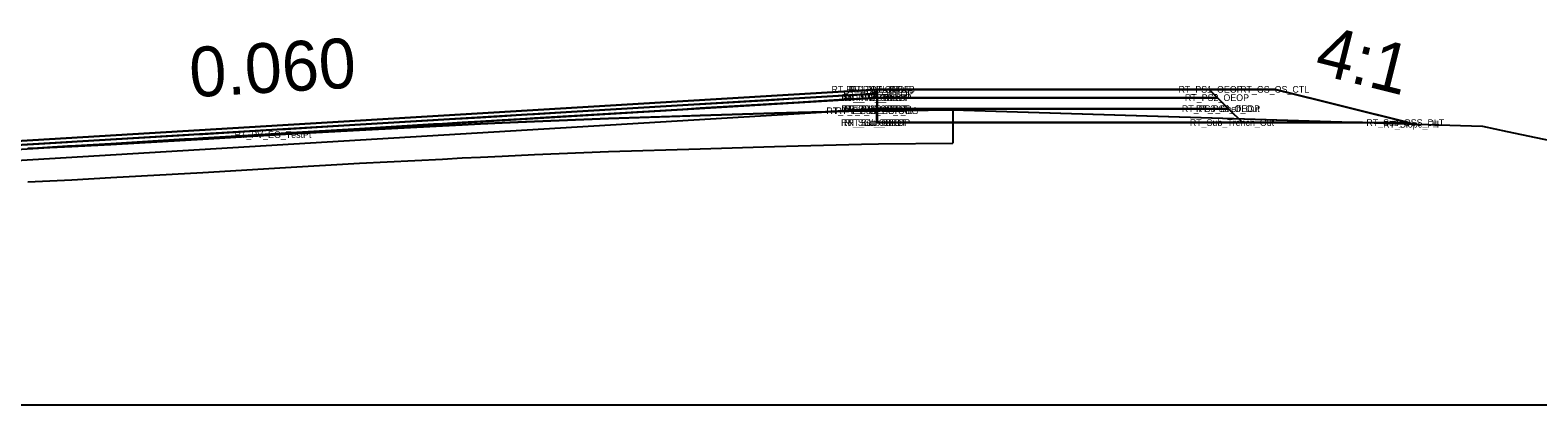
# Model space of a CAD drawing. Extents: x 2177029 to 2201446, y 59897 to 78390.
# Drawn here: x 2199283.21 to 2199328.65, y 69407.31 to 69418.59 of the extents above; entities that cross this region are included whole.
import ezdxf

# ---------------------------------------------------------------- set-up
doc = ezdxf.new("R2010")
doc.units = 0
for name, color, linetype in [('Exist Cross Section Cell', 7, 'Continuous'), ('Exist PHM Roadway Shape', 7, 'Continuous'), ('Exist XS Ground Line', 7, 'Continuous'), ('Old_Level_11', 7, 'Continuous'), ('Prop CMT Conc Surface', 7, 'Continuous'), ('Prop CMT Concrete Structures', 7, 'Continuous'), ('Prop CMT Guardrail Graphics', 7, 'Continuous'), ('Prop CMT Guardrail Widen Shoulder', 7, 'Continuous'), ('Prop CMT Pvmt Course 1', 7, 'Continuous'), ('Prop CMT Pvmt Course 1 CG', 7, 'Continuous'), ('Prop CMT Pvmt Course 2', 7, 'Continuous'), ('Prop CMT Pvmt Course 2 CG', 7, 'Continuous'), ('Prop CMT Pvmt Course 2 Wedge', 7, 'Continuous'), ('Prop CMT Pvmt Course 3', 7, 'Continuous'), ('Prop CMT Pvmt Course 4', 7, 'Continuous'), ('Prop CMT Pvmt Surface', 7, 'Continuous'), ('Prop CMT Pvmt Wedge Surface 1', 7, 'Continuous'), ('Prop CMT Slope Grass', 7, 'Continuous'), ('Prop CMT Subgrade Earthwork', 7, 'Continuous'), ('Prop Hatching', 7, 'Continuous'), ('Prop XS Side Slope Text', 7, 'Continuous'), ('Scratch_Level_0', 7, 'Continuous'), ('Scratch_Level_9', 7, 'Continuous')]:
    doc.layers.add(name, color=color, linetype=linetype)

msp = doc.modelspace()

# ---------------------------------------------------------------- linework, layer by layer
at = {"layer": 'Exist Cross Section Cell'}
msp.add_line((2199242.732, 69407.31), (2199442.732, 69407.31), dxfattribs=at)
at = {"layer": 'Exist XS Ground Line'}
msp.add_lwpolyline([(2199283.138, 69415.025), (2199284.462, 69415.09), (2199285.637, 69415.152), (2199288.411, 69415.307), (2199290.909, 69415.457), (2199293.137, 69415.583), (2199295.638, 69415.711), (2199296.227, 69415.744), (2199296.781, 69415.771), (2199297.43, 69415.802), (2199298.405, 69415.846), (2199300.637, 69415.937), (2199303.403, 69416.022), (2199305.638, 69416.094), (2199306.357, 69416.112), (2199308.264, 69416.161), (2199308.774, 69416.166), (2199311.018, 69416.191), (2199326.316, 69415.718), (2199326.976, 69415.698), (2199327.719, 69415.539), (2199346.356, 69411.643)], dxfattribs=at)
at = {"layer": 'Prop CMT Conc Surface'}
for points in [[(2199272.732, 69414.524), (2199308.732, 69416.684)], [(2199308.732, 69416.559), (2199308.732, 69416.809)], [(2199308.732, 69416.684), (2199308.732, 69416.559), (2199308.732, 69416.559)]]:
    msp.add_lwpolyline(points, dxfattribs=at)
at = {"layer": 'Prop CMT Concrete Structures'}
for p, q in [((2199272.732, 69414.649), (2199308.732, 69416.809)), ((2199308.732, 69416.809), (2199308.74, 69416.809)), ((2199308.74, 69416.809), (2199308.741, 69416.809))]:
    msp.add_line(p, q, dxfattribs=at)
at = {"layer": 'Prop CMT Guardrail Graphics'}
for points in [[(2199308.732, 69416.225), (2199308.732, 69416.809)], [(2199272.732, 69414.065), (2199308.732, 69416.225)]]:
    msp.add_lwpolyline(points, dxfattribs=at)
at = {"layer": 'Prop CMT Pvmt Course 1'}
for points in [[(2199308.732, 69416.226), (2199308.264, 69416.198), (2199307.969, 69416.18), (2199307.741, 69416.167), (2199307.176, 69416.133), (2199306.356, 69416.112), (2199305.638, 69416.094), (2199303.403, 69416.022), (2199303.138, 69416.013), (2199302.873, 69416.005), (2199300.637, 69415.937), (2199298.405, 69415.846), (2199298.138, 69415.835), (2199297.43, 69415.802), (2199296.781, 69415.771), (2199296.227, 69415.744), (2199295.638, 69415.711), (2199295.369, 69415.697), (2199293.137, 69415.583), (2199290.909, 69415.457), (2199290.638, 69415.442), (2199288.411, 69415.307), (2199288.138, 69415.291), (2199287.865, 69415.275), (2199285.637, 69415.152), (2199284.572, 69415.096), (2199284.474, 69415.091), (2199284.468, 69415.091), (2199284.462, 69415.09), (2199284.455, 69415.09), (2199284.449, 69415.09), (2199284.339, 69415.084), (2199283.281, 69415.032)], [(2199284.339, 69415.096), (2199284.449, 69415.102), (2199284.455, 69415.103), (2199284.462, 69415.103), (2199284.468, 69415.104), (2199284.474, 69415.104), (2199284.572, 69415.11), (2199285.637, 69415.174), (2199287.865, 69415.307), (2199288.138, 69415.324), (2199288.411, 69415.34), (2199290.638, 69415.474), (2199290.909, 69415.49), (2199293.137, 69415.624), (2199295.369, 69415.758), (2199295.638, 69415.774), (2199296.227, 69415.809), (2199296.781, 69415.842), (2199297.43, 69415.881), (2199298.138, 69415.924), (2199298.405, 69415.94), (2199300.637, 69416.074), (2199302.873, 69416.208), (2199303.138, 69416.224), (2199303.403, 69416.24), (2199305.638, 69416.374), (2199306.356, 69416.417), (2199307.741, 69416.5), (2199307.969, 69416.514), (2199308.264, 69416.531), (2199308.732, 69416.559)], [(2199308.732, 69416.559), (2199308.732, 69416.226)], [(2199283.281, 69415.032), (2199284.339, 69415.096)]]:
    msp.add_lwpolyline(points, dxfattribs=at)
at = {"layer": 'Prop CMT Pvmt Course 1 CG'}
for points in [[(2199308.741, 69416.226), (2199319.325, 69416.226)], [(2199308.741, 69415.809), (2199308.741, 69416.226)], [(2199319.325, 69416.226), (2199319.325, 69416.226)], [(2199319.325, 69416.226), (2199319.742, 69415.809)], [(2199319.742, 69415.809), (2199308.741, 69415.809)]]:
    msp.add_lwpolyline(points, dxfattribs=at)
at = {"layer": 'Prop CMT Pvmt Course 2'}
for points in [[(2199308.732, 69416.225), (2199308.741, 69416.226)], [(2199308.732, 69415.809), (2199308.732, 69416.225)], [(2199308.732, 69416.225), (2199308.732, 69416.225), (2199308.732, 69415.809), (2199308.732, 69415.809)], [(2199308.732, 69415.809), (2199308.732, 69416.225)], [(2199308.741, 69416.226), (2199308.741, 69415.809)], [(2199308.741, 69415.809), (2199308.732, 69415.809)]]:
    msp.add_lwpolyline(points, dxfattribs=at)
at = {"layer": 'Prop CMT Pvmt Course 2 CG'}
for points in [[(2199272.732, 69414.649), (2199308.732, 69416.809)], [(2199308.732, 69416.684), (2199272.732, 69414.524)], [(2199308.732, 69416.809), (2199308.741, 69416.809)], [(2199308.732, 69416.559), (2199308.732, 69416.809)], [(2199308.732, 69416.809), (2199308.732, 69416.559), (2199308.732, 69416.559), (2199308.732, 69416.684)], [(2199308.741, 69416.809), (2199308.741, 69416.559)], [(2199308.741, 69416.559), (2199308.732, 69416.559)]]:
    msp.add_lwpolyline(points, dxfattribs=at)
at = {"layer": 'Prop CMT Pvmt Course 2 Wedge'}
for points in [[(2199308.732, 69416.166), (2199308.264, 69416.161), (2199307.969, 69416.153), (2199307.741, 69416.147), (2199307.195, 69416.133)], [(2199307.195, 69416.133), (2199307.741, 69416.166)], [(2199307.741, 69416.166), (2199307.969, 69416.18), (2199308.264, 69416.197), (2199308.732, 69416.225)], [(2199308.732, 69416.225), (2199308.732, 69416.166)]]:
    msp.add_lwpolyline(points, dxfattribs=at)
at = {"layer": 'Prop CMT Pvmt Course 3'}
for points in [[(2199308.732, 69415.809), (2199308.717, 69416.165)], [(2199308.732, 69415.809), (2199308.741, 69415.809)], [(2199308.732, 69415.809), (2199308.732, 69415.809)], [(2199308.741, 69415.809), (2199319.742, 69415.809)], [(2199319.742, 69415.809), (2199324.742, 69415.809)]]:
    msp.add_lwpolyline(points, dxfattribs=at)
at = {"layer": 'Prop CMT Pvmt Course 4'}
msp.add_lwpolyline([(2199308.741, 69416.809), (2199318.742, 69416.809)], dxfattribs=at)
at = {"layer": 'Prop CMT Pvmt Surface'}
for points in [[(2199283.138, 69415.149), (2199284.339, 69415.221), (2199284.449, 69415.227), (2199284.455, 69415.228), (2199284.462, 69415.228), (2199284.468, 69415.229), (2199284.474, 69415.229), (2199284.572, 69415.235), (2199285.637, 69415.299), (2199287.865, 69415.432), (2199288.138, 69415.449), (2199288.411, 69415.465), (2199290.638, 69415.599), (2199290.909, 69415.615), (2199293.137, 69415.749), (2199295.369, 69415.883), (2199295.638, 69415.899), (2199296.227, 69415.934), (2199296.781, 69415.967), (2199297.43, 69416.006), (2199298.138, 69416.049), (2199298.405, 69416.065), (2199300.637, 69416.199), (2199302.873, 69416.333), (2199303.138, 69416.349), (2199303.403, 69416.365), (2199305.638, 69416.499), (2199306.356, 69416.542), (2199307.741, 69416.625), (2199307.969, 69416.639), (2199308.264, 69416.656), (2199308.732, 69416.684)], [(2199308.732, 69416.684), (2199308.732, 69416.559)], [(2199308.732, 69416.559), (2199308.264, 69416.531), (2199307.969, 69416.514), (2199307.741, 69416.5), (2199306.356, 69416.417), (2199305.638, 69416.374), (2199303.403, 69416.24), (2199303.138, 69416.224), (2199302.873, 69416.208), (2199300.637, 69416.074), (2199298.405, 69415.94), (2199298.138, 69415.924), (2199297.43, 69415.881), (2199296.781, 69415.842), (2199296.227, 69415.809), (2199295.638, 69415.774), (2199295.369, 69415.758), (2199293.137, 69415.624), (2199290.909, 69415.49), (2199290.638, 69415.474), (2199288.411, 69415.34), (2199288.138, 69415.324), (2199287.865, 69415.307), (2199285.637, 69415.174), (2199284.572, 69415.11), (2199284.474, 69415.104), (2199284.468, 69415.104), (2199284.462, 69415.103), (2199284.455, 69415.103), (2199284.449, 69415.102), (2199284.339, 69415.096), (2199283.281, 69415.032), (2199283.138, 69415.025)]]:
    msp.add_lwpolyline(points, dxfattribs=at)
at = {"layer": 'Prop CMT Pvmt Wedge Surface 1'}
for p, q in [((2199311.018, 69416.191), (2199311.018, 69415.191)), ((2199296.781, 69414.771), (2199297.43, 69414.802)), ((2199297.43, 69414.802), (2199298.405, 69414.846)), ((2199298.405, 69414.846), (2199300.637, 69414.937)), ((2199300.637, 69414.937), (2199303.403, 69415.022)), ((2199303.403, 69415.022), (2199305.638, 69415.094)), ((2199305.638, 69415.094), (2199306.357, 69415.112)), ((2199306.357, 69415.112), (2199308.264, 69415.161)), ((2199308.264, 69415.161), (2199308.774, 69415.166)), ((2199308.774, 69415.166), (2199311.018, 69415.191)), ((2199311.018, 69415.191), (2199311.018, 69415.191)), ((2199288.411, 69414.307), (2199290.909, 69414.457)), ((2199290.909, 69414.457), (2199293.137, 69414.583)), ((2199293.137, 69414.583), (2199295.638, 69414.711)), ((2199295.638, 69414.711), (2199296.227, 69414.744)), ((2199296.227, 69414.744), (2199296.781, 69414.771)), ((2199283.138, 69414.025), (2199284.462, 69414.09)), ((2199284.462, 69414.09), (2199285.637, 69414.152)), ((2199285.637, 69414.152), (2199288.411, 69414.307))]:
    msp.add_line(p, q, dxfattribs=at)
at = {"layer": 'Prop CMT Slope Grass'}
for points in [[(2199308.732, 69416.225), (2199308.732, 69416.559)], [(2199308.732, 69416.559), (2199308.741, 69416.559)], [(2199308.732, 69416.225), (2199308.732, 69416.225), (2199308.732, 69416.559), (2199308.732, 69416.559)], [(2199308.732, 69416.559), (2199308.732, 69416.225)], [(2199308.741, 69416.226), (2199308.732, 69416.225)], [(2199308.741, 69416.559), (2199308.741, 69416.226)]]:
    msp.add_lwpolyline(points, dxfattribs=at)
at = {"layer": 'Prop CMT Subgrade Earthwork'}
for points in [[(2199308.732, 69416.559), (2199308.732, 69416.809)], [(2199272.732, 69414.399), (2199308.732, 69416.559)]]:
    msp.add_lwpolyline(points, dxfattribs=at)
at = {"layer": 'Prop Hatching'}
msp.add_lwpolyline([(2199318.742, 69416.809), (2199320.742, 69416.809), (2199324.936, 69415.76)], dxfattribs=at)
at = {"layer": 'Prop XS Side Slope Text'}
msp.add_lwpolyline([(2199283.138, 69415.025), (2199284.462, 69415.09), (2199285.637, 69415.152), (2199288.411, 69415.307), (2199290.909, 69415.457), (2199293.137, 69415.583), (2199295.638, 69415.711), (2199296.227, 69415.744), (2199296.781, 69415.771), (2199297.43, 69415.802), (2199298.405, 69415.846), (2199300.637, 69415.937), (2199303.403, 69416.022), (2199305.638, 69416.094), (2199306.357, 69416.112), (2199308.264, 69416.161), (2199308.717, 69416.165), (2199311.018, 69416.191), (2199323.367, 69415.809), (2199324.742, 69415.809), (2199320.742, 69416.809), (2199318.742, 69416.809), (2199308.741, 69416.809), (2199272.732, 69414.649)], dxfattribs=at)
for points in [[(2199308.717, 69416.165), (2199311.018, 69416.191), (2199323.367, 69415.809), (2199319.742, 69415.809), (2199308.732, 69415.809)], [(2199324.742, 69415.809), (2199324.934, 69415.761), (2199323.367, 69415.809)]]:
    msp.add_lwpolyline(points, close=True, dxfattribs=at)
at = {"layer": 'Scratch_Level_0'}
for points in [[(2199308.741, 69416.559), (2199318.992, 69416.559), (2199319.325, 69416.226)], [(2199308.741, 69416.226), (2199308.741, 69416.559)], [(2199319.325, 69416.226), (2199308.741, 69416.226)]]:
    msp.add_lwpolyline(points, dxfattribs=at)
at = {"layer": 'Scratch_Level_9'}
for points in [[(2199308.741, 69416.809), (2199318.742, 69416.809), (2199318.992, 69416.559)], [(2199308.741, 69416.559), (2199308.741, 69416.809)], [(2199318.992, 69416.559), (2199308.741, 69416.559)]]:
    msp.add_lwpolyline(points, dxfattribs=at)

# ---------------------------------------------------------------- texts
at = {"layer": 'Exist PHM Roadway Shape'}
for s, p in [('RT_PV1_OTL SE LB', (2199307.359, 69416.709)), ('RT_PV2_OEEOP', (2199307.658, 69416.459)), ('RT_PV1_OEEOP', (2199307.715, 69416.584)), ('RT_PV2_OEOT', (2199307.745, 69416.459)), ('RT_PV1_OEOT', (2199307.802, 69416.709)), ('RT_PV2_OTL', (2199307.852, 69416.459)), ('RT_PV1_OTL', (2199307.908, 69416.709)), ('RT_PS1_OEOP', (2199317.818, 69416.709)), ('RT_PS2_OEOP', (2199318.011, 69416.459)), ('RT_GS_OS_CTL', (2199319.674, 69416.709)), ('RT_PV_Sub_Tie_Out', (2199307.207, 69416.065)), ('RT_PV_OEEOP_EG', (2199307.482, 69416.066)), ('RT_PV3_OEEOP', (2199307.658, 69416.125)), ('RT_PV3_OEOT', (2199307.745, 69416.125)), ('RT_PV3_OTL', (2199307.852, 69416.126)), ('RT_PS3_Shelf_Out', (2199317.919, 69416.126)), ('RT_PS3_OEOP', (2199318.344, 69416.126)), ('RT_Sub_OEEOP', (2199307.649, 69415.709)), ('RT_Sub_OEOT', (2199307.735, 69415.709)), ('RT_Sub_OTL', (2199307.842, 69415.709)), ('RT_Sub_Trench_Out', (2199318.158, 69415.709)), ('RT_Sub_OSS_DLT', (2199323.477, 69415.709)), ('RT_Slope_Fill', (2199323.984, 69415.66)), ('RT_PV_EG_TestPt', (2199289.368, 69415.347))]:
    msp.add_text(s, height=0.2, dxfattribs=at).set_placement(p)
at = {"layer": 'Old_Level_11'}
msp.add_text('0.060', height=1.5, rotation=3.4336, dxfattribs=at).set_placement((2199288.052, 69416.57))
at = {"layer": 'Prop CMT Guardrail Widen Shoulder'}
msp.add_text('4:1', height=1.5, rotation=345.9584, dxfattribs=at).set_placement((2199321.868, 69417.301))

doc.saveas('drawing.dxf')
